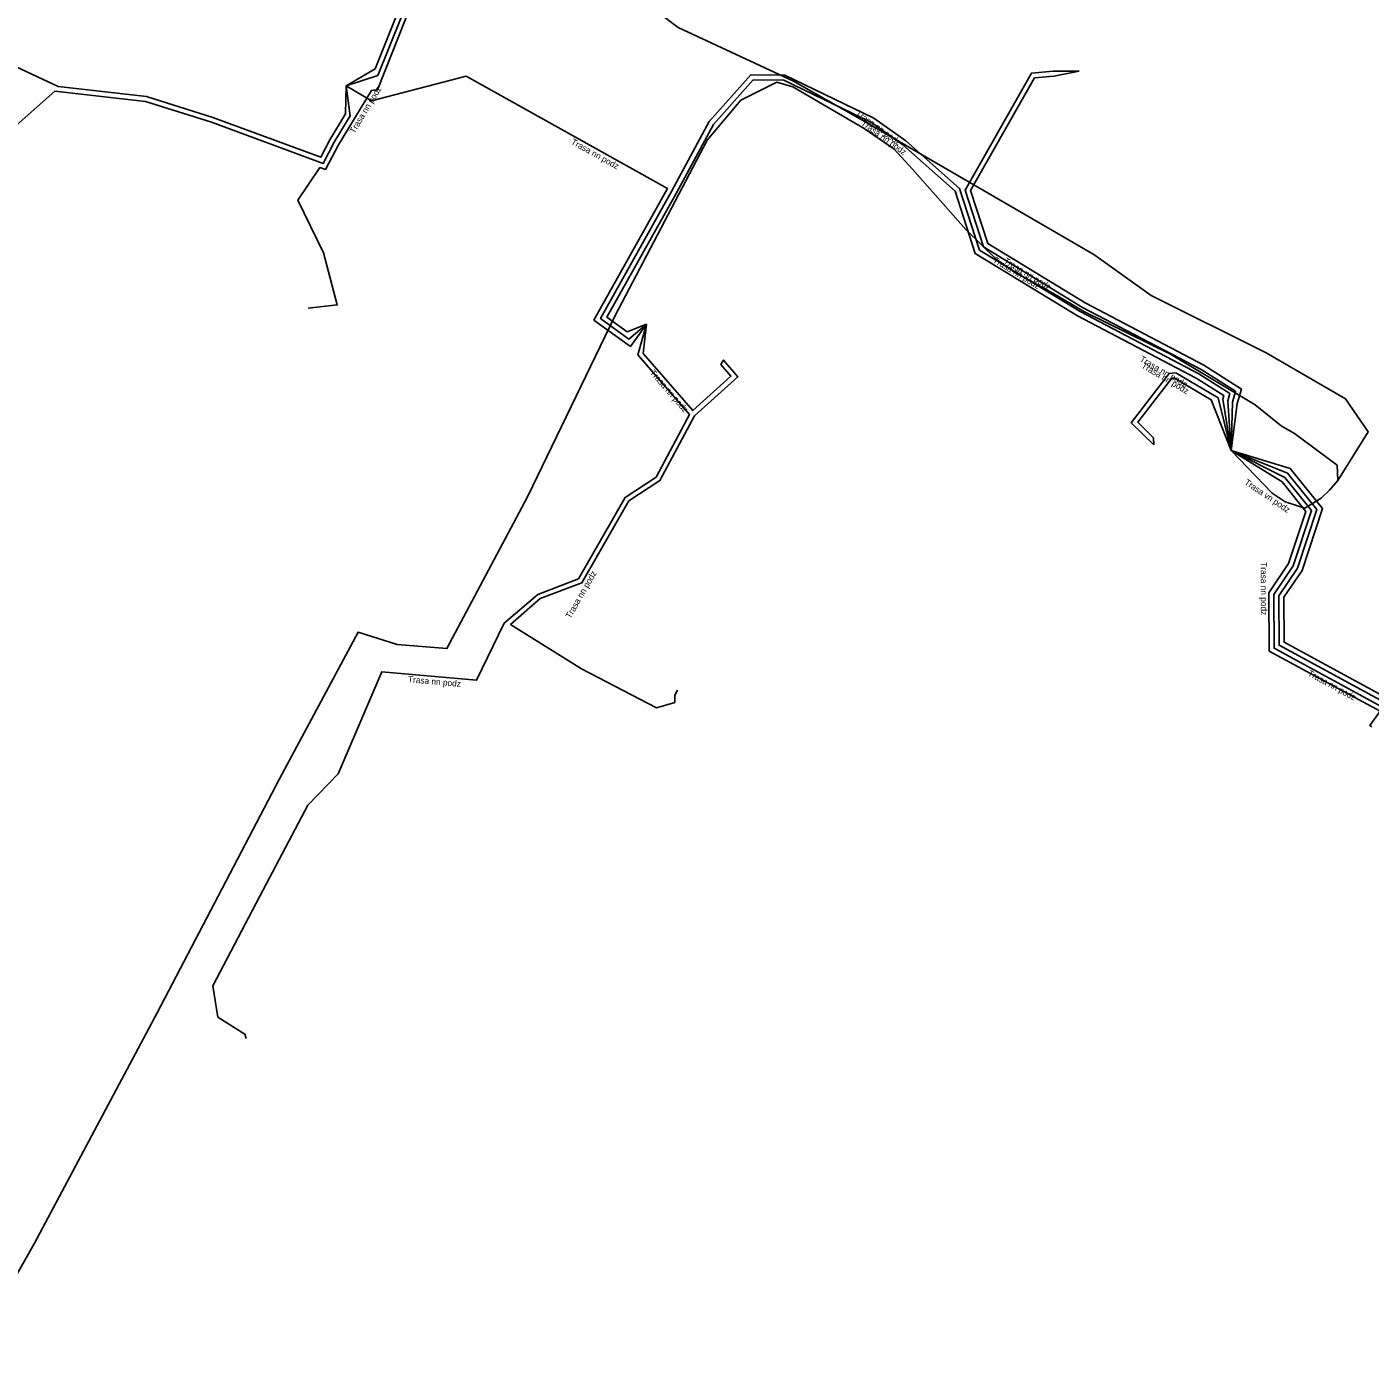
# Model space of a CAD drawing. Extents: x -528089 to -527692, y -1079306 to -1078676.
# Drawn here: x -527953.1 to -527845, y -1079189 to -1079080.7 of the extents above; entities that cross this region are included whole.
import ezdxf

# ---------------------------------------------------------------- set-up
doc = ezdxf.new("R2010")
doc.units = 0
for name, color, linetype in [('Popiskový text - Ostatní atributy Trasy', 7, 'Continuous'), ('Spojnice NN', 7, 'Continuous'), ('Spojnice VN', 7, 'Continuous')]:
    doc.layers.add(name, color=color, linetype=linetype)

msp = doc.modelspace()

# ---------------------------------------------------------------- linework, layer by layer
at = {"layer": 'Spojnice NN'}
for points in [[(-528038.84, -1079070.19), (-528033.71, -1079071.49), (-528030.41, -1079064.78), (-528028.23, -1079060.17), (-528022.79, -1079050.23), (-528016.8, -1079053.76), (-528010.47, -1079056.99), (-528004.25, -1079059.75), (-527995.58, -1079064.16), (-527988.26, -1079067.6), (-527975.06, -1079074.34), (-527965.76, -1079078.3), (-527957.79, -1079082.12), (-527950.56, -1079085.48), (-527943.45, -1079086.31), (-527938.1, -1079087.99), (-527929.42, -1079091.18), (-527928.68, -1079089.78), (-527927.43, -1079087.7), (-527927.38, -1079085.45)], [(-527927.38, -1079085.45), (-527924.84, -1079084.61), (-527922.96, -1079079.93), (-527921.94, -1079077.16), (-527923.31, -1079075.49), (-527929.84, -1079072.41), (-527932.88, -1079071.54), (-527932.52, -1079070.28), (-527940.83, -1079066.28), (-527947.4, -1079062.47), (-527949.81, -1079061.95), (-527951.65, -1079063.04)], [(-527912.78, -1079069.67), (-527913.15, -1079070.02), (-527917.1, -1079073.42), (-527921.41, -1079076.89), (-527922.59, -1079080.07), (-527924.86, -1079085.77), (-527925.35, -1079085.81), (-527927.98, -1079090.18), (-527929.05, -1079092.17), (-527929.49, -1079092.01), (-527931.27, -1079094.63), (-527929.21, -1079098.88), (-527928.09, -1079103.07), (-527930.43, -1079103.32)], [(-527927.38, -1079085.45), (-527925.04, -1079084.06), (-527923.33, -1079079.79), (-527922.4, -1079077.24), (-527923.57, -1079075.81), (-527929.98, -1079072.79), (-527932.04, -1079072.19), (-527932.79, -1079073.84), (-527933.42, -1079073.63)], [(-527903.22, -1079104.62), (-527904.5, -1079106.4), (-527907.44, -1079104.28), (-527901.52, -1079093.71), (-527917.71, -1079084.66), (-527925.34, -1079086.64), (-527927.38, -1079085.45)], [(-527903.22, -1079104.62), (-527904.63, -1079105.81), (-527906.91, -1079104.17), (-527901.18, -1079093.9), (-527898.17, -1079088.32), (-527894.82, -1079084.56), (-527892.07, -1079084.57), (-527884.91, -1079088.04), (-527882.35, -1079089.87), (-527878.03, -1079093.69), (-527876.43, -1079098.66), (-527868.33, -1079103.6), (-527858.77, -1079108.61), (-527856.28, -1079110.19), (-527856.45, -1079110.77), (-527856.17, -1079114.78)], [(-527903.22, -1079104.62), (-527904.76, -1079105.22), (-527906.39, -1079104.05), (-527900.82, -1079094.1), (-527897.83, -1079088.55), (-527894.64, -1079084.96), (-527892.17, -1079084.97), (-527885.11, -1079088.38), (-527882.6, -1079090.19), (-527878.38, -1079093.92), (-527876.76, -1079098.93), (-527868.53, -1079103.95), (-527858.98, -1079108.95), (-527856.75, -1079110.36), (-527856.84, -1079110.65), (-527856.17, -1079114.78)], [(-527868.4, -1079084.27), (-527870.48, -1079084.26), (-527872.23, -1079084.42), (-527877.57, -1079093.83), (-527876.09, -1079098.4), (-527868.13, -1079103.26), (-527858.58, -1079108.26), (-527855.82, -1079110.01), (-527856.07, -1079110.88), (-527856.17, -1079114.78)], [(-527868.4, -1079084.27), (-527870.45, -1079084.66), (-527871.99, -1079084.8), (-527877.14, -1079093.87), (-527875.76, -1079098.13), (-527867.93, -1079102.91), (-527858.38, -1079107.91), (-527855.35, -1079109.83), (-527855.68, -1079110.99), (-527856.17, -1079114.78)], [(-527927.38, -1079085.45), (-527927.06, -1079087.85), (-527928.33, -1079089.98), (-527929.23, -1079091.68), (-527938.22, -1079088.37), (-527943.53, -1079086.71), (-527950.81, -1079085.86), (-527954.39, -1079089.02), (-527957.67, -1079092.7), (-527961.42, -1079099.26), (-527966.4, -1079108.98), (-527968.51, -1079109.76), (-527977.2, -1079104.46), (-527978.49, -1079106.15)], [(-527935.43, -1079162.09), (-527935.52, -1079161.73), (-527937.7, -1079160.36), (-527938.1, -1079157.85), (-527934.32, -1079150.62), (-527930.45, -1079143.32), (-527928.02, -1079140.78), (-527924.51, -1079132.58), (-527916.88, -1079133.26), (-527914.65, -1079128.68), (-527911.96, -1079126.35), (-527908.69, -1079125.11), (-527904.92, -1079118.55), (-527902.43, -1079116.92), (-527899.75, -1079111.89), (-527903.9, -1079107.09), (-527903.22, -1079104.62)], [(-527903.22, -1079104.62), (-527903.48, -1079106.97), (-527899.49, -1079111.57), (-527896.42, -1079108.8), (-527897.23, -1079107.86), (-527897.12, -1079107.68)], [(-527900.71, -1079134.07), (-527900.92, -1079134.46), (-527900.94, -1079135.05), (-527902.41, -1079135.47), (-527908.43, -1079132.33), (-527914.15, -1079128.77), (-527911.76, -1079126.69), (-527908.41, -1079125.43), (-527904.62, -1079118.83), (-527902.13, -1079117.2), (-527899.35, -1079111.99), (-527895.86, -1079108.84), (-527897.01, -1079107.5), (-527897.12, -1079107.68)], [(-527856.17, -1079114.78), (-527857.22, -1079110.54), (-527860.62, -1079108.54), (-527861.15, -1079108.57), (-527864.22, -1079112.55), (-527862.4, -1079114.33)], [(-527856.17, -1079114.78), (-527857.78, -1079110.69), (-527860.72, -1079108.95), (-527860.94, -1079108.96), (-527863.69, -1079112.51), (-527862.41, -1079113.76), (-527862.4, -1079114.33)], [(-527802.96, -1079145.22), (-527803.95, -1079146.01), (-527809.32, -1079154.23), (-527811.15, -1079154.64), (-527816.43, -1079150.79), (-527827.7, -1079143.79), (-527843.56, -1079135.19), (-527852.32, -1079130.44), (-527852.33, -1079126.47), (-527850.83, -1079124.24), (-527849.28, -1079119.53), (-527851.64, -1079116.59), (-527856.17, -1079114.78)], [(-527856.17, -1079114.78), (-527851.86, -1079116.95), (-527849.72, -1079119.61), (-527851.19, -1079124.06), (-527852.73, -1079126.35), (-527852.72, -1079130.68), (-527843.76, -1079135.55), (-527826.22, -1079145.04), (-527827.11, -1079147.83)], [(-527856.17, -1079114.78), (-527852.08, -1079117.31), (-527850.17, -1079119.69), (-527851.55, -1079123.88), (-527853.13, -1079126.23), (-527853.12, -1079130.92), (-527844.19, -1079135.76), (-527845.02, -1079136.9), (-527844.85, -1079137)], [(-527802.96, -1079145.22), (-527804.28, -1079145.78), (-527809.57, -1079153.88), (-527811.06, -1079154.21), (-527816.2, -1079150.46), (-527827.5, -1079143.44), (-527843.37, -1079134.84), (-527851.92, -1079130.2), (-527851.93, -1079126.59), (-527850.47, -1079124.42), (-527848.83, -1079119.45), (-527851.42, -1079116.23), (-527856.17, -1079114.78)]]:
    msp.add_lwpolyline(points, dxfattribs=at)
at = {"layer": 'Spojnice VN'}
for points in [[(-527847.58, -1079117.19), (-527845.14, -1079113.27), (-527846.96, -1079110.62), (-527853.36, -1079106.93), (-527862.61, -1079102.31), (-527867.21, -1079099.01), (-527885.37, -1079088.47), (-527891.38, -1079085.06), (-527900.67, -1079080.75), (-527902.31, -1079079.5)], [(-527847.58, -1079117.19), (-527845.14, -1079113.27), (-527846.96, -1079110.62), (-527853.36, -1079106.93), (-527862.61, -1079102.31), (-527867.21, -1079099.01), (-527885.37, -1079088.47), (-527891.38, -1079085.06), (-527900.67, -1079080.75), (-527902.31, -1079079.5)], [(-527847.58, -1079117.19), (-527847.64, -1079115.97), (-527851.07, -1079113.41), (-527852.15, -1079112.78), (-527854.24, -1079111.09), (-527861.06, -1079107.03), (-527867.97, -1079103.63), (-527870.52, -1079102.12), (-527873.51, -1079100.49), (-527875.06, -1079099.41), (-527877.52, -1079096.99), (-527881.85, -1079092.11), (-527883.29, -1079090.53), (-527885.69, -1079088.87), (-527891.43, -1079085.51), (-527892.73, -1079085.14), (-527895.63, -1079086.6), (-527898.33, -1079089.81), (-527905.76, -1079103.97), (-527912.79, -1079118.51), (-527919.27, -1079130.72), (-527923.27, -1079130.38), (-527926.42, -1079129.4), (-527932.73, -1079141.18), (-527942.58, -1079160.03), (-527952.46, -1079178.54), (-527958.37, -1079189)], [(-527856.17, -1079114.78), (-527852.86, -1079118.21), (-527851.84, -1079118.9), (-527850.25, -1079119.42), (-527848.92, -1079118.6), (-527848.26, -1079117.96), (-527847.58, -1079117.19)]]:
    msp.add_lwpolyline(points, dxfattribs=at)

# ---------------------------------------------------------------- texts
at = {"layer": 'Popiskový text - Ostatní atributy Trasy'}
for s, rotation, p in [('Trasa nn podz', 58.9726, (-527926.71, -1079089.32)), ('Trasa nn podz', 324.2822, (-527886.43, -1079087.75)), ('Trasa nn podz', 324.2575, (-527885.99, -1079088.55)), ('Trasa nn podz', 330.8016, (-527909.33, -1079090.09)), ('Trasa nn podz', 328.6074, (-527875.39, -1079099.59)), ('Trasa nn podz', 328.6063, (-527874.51, -1079099.66)), ('Trasa nn podz', 329.5264, (-527863.57, -1079107.56)), ('Trasa nn podz', 329.3985, (-527863.44, -1079108.09)), ('Trasa nn podz', 310.8665, (-527902.98, -1079108.54)), ('Trasa vn podz', 325.9228, (-527855.15, -1079117.45)), ('Trasa nn podz', 270.1344, (-527853.79, -1079123.76)), ('Trasa nn podz', 60.1244, (-527909.33, -1079128.34)), ('Trasa nn podz', 354.8977, (-527922.42, -1079133.42)), ('Trasa nn podz', 331.503, (-527850.06, -1079132.86))]:
    msp.add_text(s, height=0.5, rotation=rotation, dxfattribs=at).set_placement(p)

doc.saveas('drawing.dxf')
